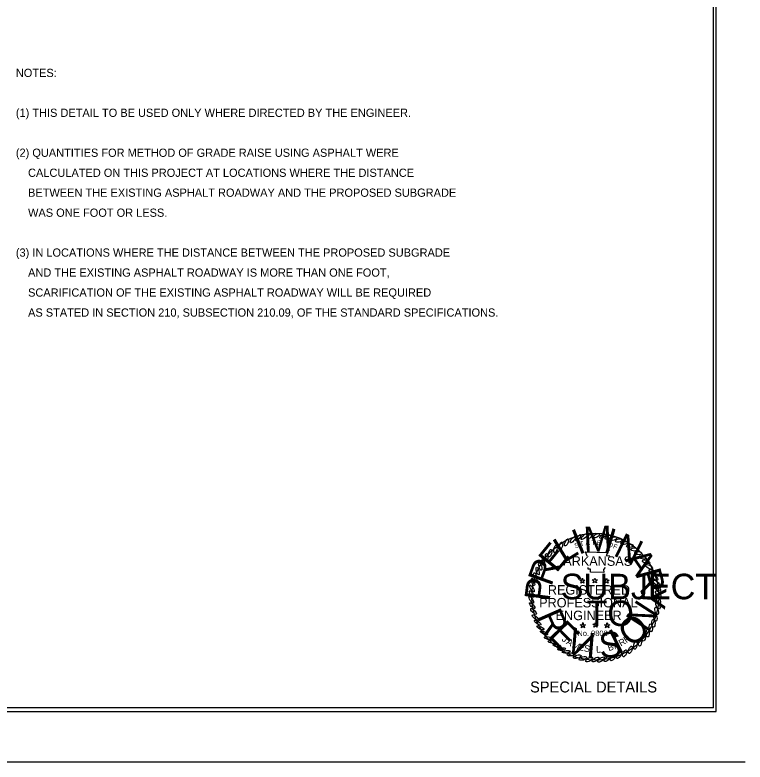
# Model space of a CAD drawing. Extents: x 714919 to 718439, y 1619644 to 1621844.
# Drawn here: x 717373 to 718439, y 1619644 to 1620734 of the extents above; entities that cross this region are included whole.
import ezdxf

# ---------------------------------------------------------------- set-up
doc = ezdxf.new("R2010")
doc.units = 0
for name, color, linetype in [('R_Annotation', 7, 'Continuous'), ('R_Border', 7, 'Continuous'), ('R_Border Notes', 7, 'Continuous'), ('R_Border PE', 7, 'Continuous'), ('R_Border Prem', 7, 'Continuous'), ('R_No Plot', 7, 'Continuous')]:
    doc.layers.add(name, color=color, linetype=linetype)

msp = doc.modelspace()

# ---------------------------------------------------------------- linework, layer by layer
at = {"layer": 'R_Border'}
for p, q in [((718393.2, 1619722.5), (718393.1, 1621777.1)), ((718393.2, 1619722.5), (715231.2, 1619722.5)), ((714919.1, 1619643.5), (718439.3, 1619643.8))]:
    msp.add_line(p, q, dxfattribs=at)
at = {"layer": 'R_Border PE'}
for points in [[(718208.6, 1619943.8), (718206.5, 1619950.3), (718239.1, 1619949.4), (718236.7, 1619945), (718241.7, 1619944.7), (718241.4, 1619944.1)], [(718235.2, 1619927.5), (718232.5, 1619924.6), (718233.1, 1619920.1), (718213.6, 1619920.7), (718213.6, 1619924.9), (718210.1, 1619924.9), (718210.1, 1619927.5)]]:
    msp.add_lwpolyline(points, dxfattribs=at)
for points in [[(718201.8, 1619911.8), (718202.7, 1619908.9), (718205.6, 1619908.9), (718203.2, 1619907.4), (718204.1, 1619904.4), (718201.8, 1619906.2), (718199.4, 1619904.4), (718200.3, 1619907.4), (718197.9, 1619908.9), (718200.9, 1619908.9)], [(718220.1, 1619912.1), (718221, 1619909.5), (718223.7, 1619909.5), (718221.6, 1619907.7), (718222.5, 1619905), (718220.1, 1619906.5), (718217.7, 1619905), (718218.6, 1619907.7), (718216.3, 1619909.5), (718219.2, 1619909.5)], [(718237, 1619911.8), (718237.9, 1619908.9), (718240.8, 1619908.9), (718238.5, 1619907.4), (718239.4, 1619904.4), (718237, 1619906.2), (718234.6, 1619904.4), (718235.5, 1619907.4), (718233.1, 1619908.9), (718236.1, 1619908.9)], [(718202.7, 1619847), (718203.5, 1619844), (718206.5, 1619844), (718204.1, 1619842.6), (718205, 1619839.6), (718202.7, 1619841.4), (718200.3, 1619839.6), (718201.2, 1619842.6), (718198.8, 1619844), (718201.8, 1619844)], [(718221, 1619847.3), (718221.9, 1619844.6), (718224.6, 1619844.6), (718222.2, 1619842.9), (718223.4, 1619840.2), (718221, 1619841.7), (718218.6, 1619840.2), (718219.5, 1619842.9), (718217.2, 1619844.6), (718220.1, 1619844.6)], [(718237.9, 1619847), (718238.8, 1619844), (718241.7, 1619844), (718239.4, 1619842.6), (718240.2, 1619839.6), (718237.9, 1619841.4), (718235.5, 1619839.6), (718236.4, 1619842.6), (718234, 1619844), (718237, 1619844)]]:
    msp.add_lwpolyline(points, close=True, dxfattribs=at)
for centre, major_axis, ratio in [((718195.9, 1619970.9), (-3.64, -4.4), 0.329518), ((718204.7, 1619972.7), (-4.59, -4.21), 0.348728), ((718213, 1619973.2), (-3.87, -3.02), 0.44237), ((718222.7, 1619974), (-4.21, -2.45), 0.475469), ((718231.4, 1619973.1), (-4.21, -2.45), 0.475469), ((718170.5, 1619959.1), (-1.53, -5.49), 0.375751), ((718178.8, 1619964), (-2.46, -5.15), 0.329518), ((718187.8, 1619967.9), (-3.58, -4.44), 0.329518), ((718239.5, 1619971.7), (-4.21, -2.45), 0.475469), ((718247.5, 1619969.7), (-4.64, -1.48), 0.475469), ((718255, 1619966.8), (-4.79, -0.89), 0.475469), ((718262.8, 1619963.3), (-4.85, -0.42), 0.475469), ((718154.6, 1619948.3), (-1.53, -5.49), 0.391724), ((718162.5, 1619954.6), (-1.53, -5.49), 0.394697), ((718271.1, 1619959), (-4.85, -0.42), 0.475469), ((718277.7, 1619953.8), (-4.87, 0.11), 0.475469), ((718149.5, 1619942.2), (0, -5.7), 0.322879), ((718283.3, 1619948.5), (-5.09, 0.7), 0.451028), ((718289.6, 1619942.2), (-5.17, 1.18), 0.436264), ((718140.3, 1619928.9), (1.57, -5.48), 0.322879), ((718144.7, 1619936.1), (0, -5.7), 0.322879), ((718294.8, 1619935.8), (-5.3, 1.59), 0.418512), ((718299.1, 1619928.6), (-4.99, 2.77), 0.40589), ((718136.5, 1619922.3), (1.57, -5.48), 0.322879), ((718304.1, 1619920.7), (-4.66, 3.28), 0.40589), ((718129.9, 1619906.3), (1.57, -5.48), 0.322879), ((718133, 1619914.3), (1.57, -5.48), 0.322879), ((718307.2, 1619912.7), (-4.3, 3.75), 0.40589), ((718128.2, 1619896.8), (3.04, -4.83), 0.322879), ((718309.8, 1619904.9), (-4.3, 3.75), 0.40589), ((718311.6, 1619897.2), (-4.1, 3.96), 0.40589), ((718127.7, 1619888.8), (3.04, -4.83), 0.322879), ((718312.4, 1619888.9), (-3.5, 4.5), 0.40589), ((718127.2, 1619880.4), (3.04, -4.83), 0.322879), ((718312.1, 1619872.1), (-2.3, 5.22), 0.40589), ((718312.6, 1619880.6), (-2.77, 4.99), 0.40589), ((718128.6, 1619871.7), (3.92, -4.14), 0.322879), ((718130.5, 1619863.4), (3.92, -4.14), 0.322879), ((718310.1, 1619864.3), (-1.48, 5.51), 0.40589), ((718133.1, 1619854.5), (4.29, -3.76), 0.322879), ((718308.3, 1619854.8), (-1.02, 5.61), 0.40589), ((718136.4, 1619847), (4.67, -3.27), 0.322879), ((718301.7, 1619839.4), (-0.33, 5.69), 0.40589), ((718305.5, 1619846.1), (-0.33, 5.69), 0.40589), ((718140.6, 1619839.3), (5.13, -2.49), 0.322879), ((718145.9, 1619832), (5.13, -2.49), 0.322879), ((718297.2, 1619831.8), (0.27, 5.7), 0.40589), ((718151.9, 1619824.4), (5.58, -1.19), 0.322879), ((718286, 1619818.5), (0.91, 5.63), 0.40589), ((718291.5, 1619825.6), (0.91, 5.63), 0.40589), ((718157.6, 1619818.6), (5.58, -1.19), 0.322879), ((718164.6, 1619813.6), (5.58, -1.19), 0.322879), ((718271.8, 1619807.3), (2.26, 5.24), 0.40589), ((718279.1, 1619813.7), (1.36, 5.54), 0.40589), ((718171.5, 1619808.4), (5.68, 0.48), 0.322879), ((718178.1, 1619804.5), (5.68, 0.48), 0.322879), ((718185.3, 1619800.7), (5.68, 0.48), 0.40589), ((718255.3, 1619799.4), (3.39, 4.59), 0.40589), ((718263.7, 1619802.2), (2.43, 5.16), 0.40589), ((718194.3, 1619797.3), (5.5, 1.52), 0.40589), ((718202.6, 1619794.7), (5.5, 1.52), 0.40589), ((718211.8, 1619793.3), (4.91, 2.91), 0.40589), ((718221, 1619793.2), (4.91, 2.91), 0.40589), ((718229.1, 1619793.1), (4.63, 3.33), 0.40589), ((718238.2, 1619794.3), (4.36, 3.68), 0.40589), ((718246.7, 1619795.7), (4.08, 3.98), 0.40589)]:
    msp.add_ellipse(centre, major_axis=major_axis, ratio=ratio, dxfattribs=at)
at = {"layer": 'R_Border Prem'}
msp.add_circle((718220.8, 1619884.8), 92.6, dxfattribs=at)
at = {"layer": 'R_No Plot'}
msp.add_lwpolyline([(715227.2, 1619717.3), (718397.1, 1619717.4), (718397.2, 1621782.5), (715227.1, 1621782.3)], close=True, dxfattribs=at)

# ---------------------------------------------------------------- texts
at = {"layer": 'R_Annotation'}
for s, p in [('NOTES:', (717374.8, 1620643.2)), ('(1) THIS DETAIL TO BE USED ONLY WHERE DIRECTED BY THE ENGINEER.', (717374.8, 1620585)), ('(2) QUANTITIES FOR METHOD OF GRADE RAISE USING ASPHALT WERE', (717374.8, 1620526.7)), ('    CALCULATED ON THIS PROJECT AT LOCATIONS WHERE THE DISTANCE', (717374.8, 1620497.5)), ('    BETWEEN THE EXISTING ASPHALT ROADWAY AND THE PROPOSED SUBGRADE', (717374.8, 1620468.4)), ('    WAS ONE FOOT OR LESS.', (717374.8, 1620439.2)), ('(3) IN LOCATIONS WHERE THE DISTANCE BETWEEN THE PROPOSED SUBGRADE', (717374.8, 1620381)), ('    AND THE EXISTING ASPHALT ROADWAY IS MORE THAN ONE FOOT,', (717374.8, 1620351.8)), ('    SCARIFICATION OF THE EXISTING ASPHALT ROADWAY WILL BE REQUIRED', (717374.8, 1620322.7)), ('    AS STATED IN SECTION 210, SUBSECTION 210.09, OF THE STANDARD SPECIFICATIONS.', (717374.8, 1620293.5))]:
    msp.add_text(s, height=12, dxfattribs=at).set_placement(p)
at = {"layer": 'R_Border Notes'}
msp.add_text('SPECIAL DETAILS', height=16, rotation=359.9984, dxfattribs=at).set_placement((718125.4, 1619745.1))
at = {"layer": 'R_Border PE'}
for s, height, rotation, p in [('T', 6.91, 14.9614, (718199.1, 1619958)), ('A', 6.91, 5.7216, (718206.5, 1619959.8)), ('T', 6.91, 1.1017, (718214.8, 1619960.4)), ('E', 6.91, 356.4818, (718222.8, 1619960.4)), ('S', 6.91, 19.5814, (718191.7, 1619955.6)), ('O', 6.91, 342.6221, (718238.2, 1619958.3)), ('F', 6.91, 338.0022, (718245.9, 1619955.9)), ('ARKANSAS', 13.81, 360, (718173.9, 1619929.9)), ('REGISTERED', 13.81, 360, (718151.4, 1619887.9)), ('PROFESSIONAL', 13.814, 360, (718138.7, 1619869.2)), ('ENGINEER', 13.81, 360, (718162.7, 1619850.6)), ('No. 9808', 7.89, 360, (718194.5, 1619827.5)), ('J', 9.6, 322.4167, (718170.9, 1619821.2)), ('R', 9.6, 29.6215, (718258.1, 1619812)), ('R', 9.6, 35.2219, (718266, 1619816.8)), ('A', 9.6, 328.0171, (718177.4, 1619816.4)), ('M', 9.6, 333.6175, (718185.7, 1619811.6)), ('E', 9.6, 344.8183, (718195.2, 1619807.5)), ('S', 9.6, 350.4187, (718203.6, 1619805.1)), ('L', 9.6, 1.6195, (718221.9, 1619803.2)), ('B', 9.6, 18.4207, (718240.5, 1619805.3)), ('A', 9.6, 24.0211, (718249.3, 1619808)), ('.', 9.6, 7.2199, (718230.8, 1619803.8))]:
    msp.add_text(s, height=height, rotation=rotation, dxfattribs=at).set_placement(p)
at = {"layer": 'R_Border Prem'}
for s, height, rotation, p in [('M', 37.2, 2.6943, (718204.4, 1619949.6)), ('I', 37.2, 22.0105, (718196.3, 1619945.5)), ('I', 37.2, 343.3781, (718230.7, 1619950.2)), ('N', 37.2, 333.7199, (718245.3, 1619945.7)), ('E', 37.2, 50.9849, (718163.7, 1619918.3)), ('L', 37.2, 31.6686, (718174.7, 1619933.3)), ('A', 37.2, 304.7456, (718262.8, 1619939.1)), ('R', 37.2, 70.3011, (718156.3, 1619898.7)), ('R', 37.2, 285.4294, (718278.9, 1619920.3)), ('P', 37.2, 82.6089, (718153.8, 1619877)), ('SUBJECT', 37.24, 360, (718170.2, 1619881.1)), ('Y', 37.2, 266.1131, (718287.5, 1619900.3)), ('TO', 37.24, 360, (718207.8, 1619842)), ('N', 37.2, 57.1378, (718294.5, 1619832.4)), ('R', 37.2, 293.7639, (718134.5, 1619856.7)), ('O', 37.2, 36.5754, (718271.8, 1619810.2)), ('E', 37.2, 314.3262, (718150.5, 1619827.5)), ('V', 37.2, 334.8885, (718173.6, 1619807.2)), ('S', 37.2, 5.732, (718227.9, 1619794.8)), ('I', 37.2, 26.2943, (718252.9, 1619799.9)), ('I', 37.2, 355.4508, (718206.4, 1619795.4))]:
    msp.add_text(s, height=height, rotation=rotation, dxfattribs=at).set_placement(p)

doc.saveas('drawing.dxf')
